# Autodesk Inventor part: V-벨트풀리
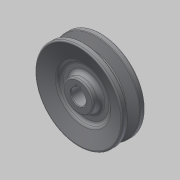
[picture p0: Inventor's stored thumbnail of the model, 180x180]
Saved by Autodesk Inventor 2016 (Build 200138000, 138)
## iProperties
Created: 2016-08
Part Number: V-벨트풀리
Material: 알루미늄 6061
Document SubType Name: Modeling
Designer: mduedu
Density: 2.71 g/cm^3
Appearance: 기본값
Author: mduedu
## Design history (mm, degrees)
sketch "스케치1"
  geometry: L1 (0, 9.5)-(0, -9.5); L2 (0, 9.5)-(35, 9.5); L3 (35, 9.5)-(35, 4.825); L4 (35, 4.825)-(26, 2.074); L5 (26, 2.074)-(26, 0); L6 (0, 0)-(26, 0); L7 (0, -9.5)-(35, -9.5); L8 (35, -9.5)-(35, -4.825); L9 (35, -4.825)-(26, -2.074); L10 (26, -2.074)-(26, 0); L11 (32.3, 9.5)-(32.3, -9.5); 3 further points
  constraints: 22 end point, 6 point on line, 4 perpendicular, 3 symmetric about line, 1 coincident, 1 horizontal alignment, 1 midpoint, 1 parallel, 1 vertical
  dimensions: "d0" = 19 distance of L1.start L1.end; "d2" = 70 diameter of L8 L1; "d4" = 6.3 distance between parallel lines of L10 L11; "d5" = 2.7 distance between parallel lines of L11 L8; "d6" = 8 distance of point (32.3, -4) point (32.3, 4); "d7" = 34 deg angle of L9 L4
revolve "회전1" sketch "스케치1" stored, may be unused: angle "d8" = 90 deg
sketch "스케치2"
  geometry: L1 (-2, 0)-(2, 0); L2 (2, 0)-(2, 7.8); L3 (2, 7.8)-(-2, 7.8); L4 (-2, 7.8)-(-2, 0); C1 r 6 at (0, 0); 2 further points
  constraints: 8 end point, 2 coincident, 2 parallel, 1 centre point, 1 horizontal, 1 midpoint, 1 perpendicular
  dimensions: "d9" = 12 diameter of C1; "d11" = 4 distance of L2.end L3.end; "d12" = 7.8 distance of L1.end L2.end
extrude "돌출1" cut sketch "스케치2" stored distance "d13" = 10; taper "d14" = 0 deg
sketch "스케치3"
  geometry: L1 (35, 4.825)-(26, 2.074) reference; L2 (26, 2.074)-(26, -2.074) reference; L3 (0, 0)-(26, 0); L4 (35, 9.5)-(35, 4.825) reference; L5 (-35, 9.5)-(35, 9.5) reference; L6 (35, 9.5)-(21, 5.22); L7 (21, 5.22)-(21, 3); L8 (21, 3)-(12, 3); L9 (12, 3)-(12, 9.5); L10 (0, 9.5)-(0, -9.5); L11 (5.657, -9.5)-(-6, -9.5) reference; L12 (12, 9.5)-(35, 9.5)
  constraints: 14 end point, 3 midpoint, 2 parallel, 2 perpendicular, 2 point on line, 1 collinear, 1 horizontal
  dimensions: "d15" = 3 distance between parallel lines of L3 L8; "d17" = 42 diameter of L7 L10; "d18" = 24 diameter of L9 L10
revolve "회전2" sketch "스케치3" stored, may be unused: angle "d19" = 90 deg
fillet "모깎기1" dims "d20" = 0.5, "d21" = 1, "d22" = 1
fillet "모깎기2" dims "d23" = 3
fillet "모깎기3" dims "d24" = 3
fillet "모깎기4" dims "d25" = 3
chamfer "모따기1" distance "d26" = 0.5; stored, may be unused: second distance "d27" = 2, angle "d28" = 45 deg
fillet "모깎기5" dims "d29" = 1
node "솔리드1"
mirror "대칭1"
